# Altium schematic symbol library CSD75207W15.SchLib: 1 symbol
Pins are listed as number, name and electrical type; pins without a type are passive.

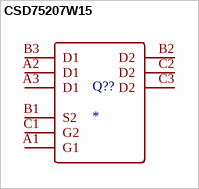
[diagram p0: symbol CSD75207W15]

## CSD75207W15
designator Q??
footprint DSBGA-9_L1.5-W1.5-R3-C3-P0.50-BL
pins: A1 G1, A2 D1, A3 D1, B1 S2, B2 D2, B3 D1, C1 G2, C2 D2, C3 D2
